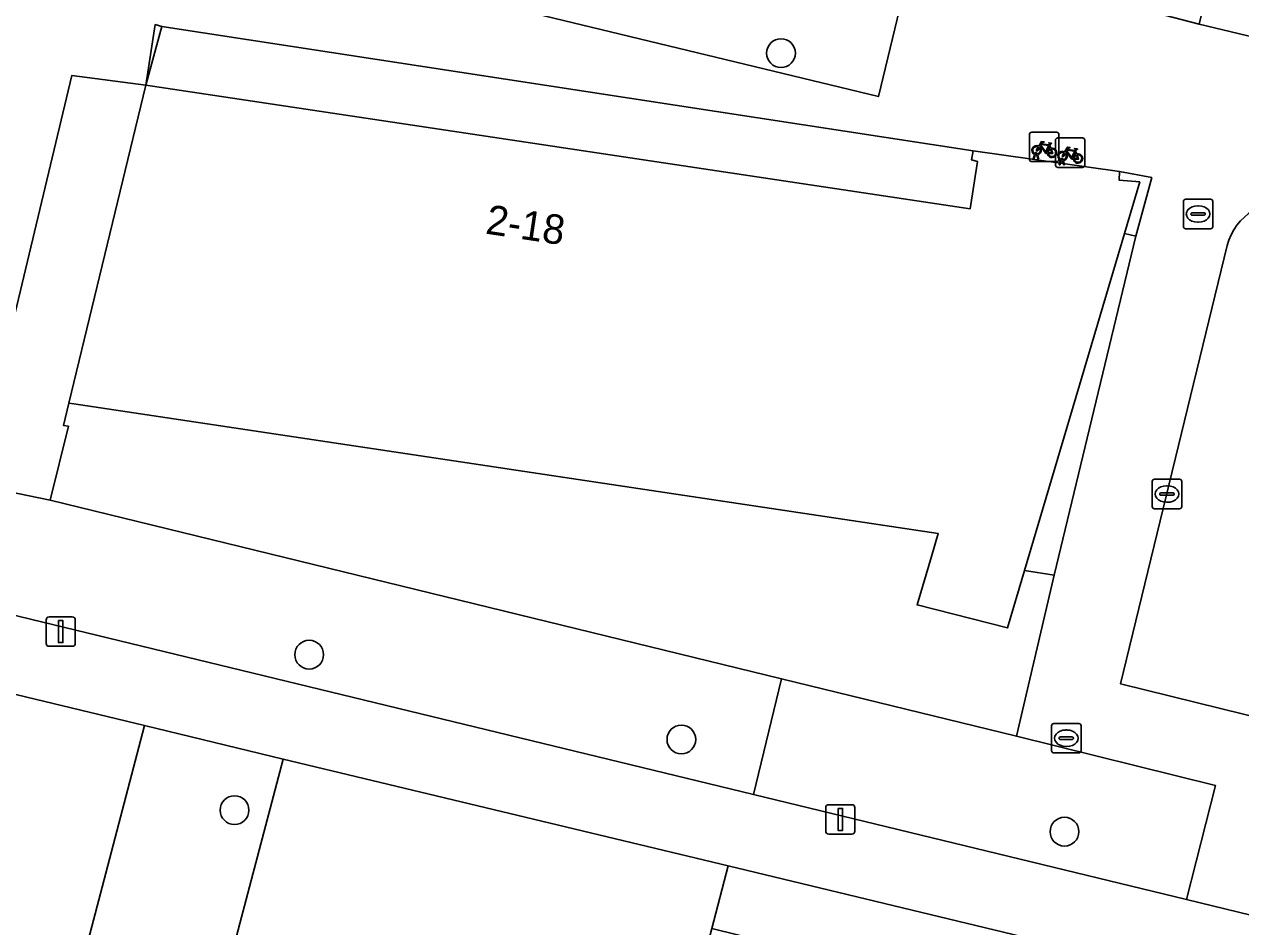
# Model space of a CAD drawing. Extents: x 162803 to 163818, y 381639 to 382475.
# Drawn here: x 163271.29 to 163312.66, y 382163.26 to 382193.93 of the extents above; entities that cross this region are included whole.
import ezdxf

# ---------------------------------------------------------------- set-up
doc = ezdxf.new("R2010")
doc.units = 0
for name, color, linetype in [('IMGEO_Boom', 7, 'Continuous'), ('IMGEO_Erf', 7, 'Continuous'), ('IMGEO_Fietsenrek', 7, 'Continuous'), ('IMGEO_Groenvoorziening', 7, 'Continuous'), ('IMGEO_Hek', 7, 'Continuous'), ('IMGEO_Kolk', 7, 'Continuous'), ('IMGEO_Lichtmast', 7, 'Continuous'), ('IMGEO_Pand', 7, 'Continuous'), ('IMGEO_Pand_nummerreeks', 7, 'Continuous'), ('IMGEO_Pand_overbouw', 7, 'Continuous'), ('IMGEO_Parkeervlak_open', 7, 'Continuous'), ('IMGEO_Rijbaan_lokaal_open', 7, 'Continuous'), ('IMGEO_Rioolput', 7, 'Continuous'), ('IMGEO_Voetpad_gesloten', 7, 'Continuous'), ('IMGEO_Voetpad_open', 7, 'Continuous')]:
    doc.layers.add(name, color=color, linetype=linetype)

msp = doc.modelspace()

# ---------------------------------------------------------------- linework, layer by layer
at = {"layer": 'IMGEO_Boom'}
for centre in [(163297.026, 382192.949), (163280.98, 382172.501), (163293.637, 382169.621), (163278.441, 382167.218), (163306.664, 382166.486)]:
    msp.add_circle(centre, 0.489, dxfattribs=at)
at = {"layer": 'IMGEO_Erf'}
msp.add_lwpolyline([(163272.981, 382181.029), (163272.811, 382181.055), (163272.627, 382180.291), (163272.792, 382180.266), (163272.171, 382177.751), (163297.042, 382171.68), (163305.036, 382169.729), (163306.317, 382175.199), (163305.301, 382175.36), (163304.723, 382173.413), (163301.65, 382174.195), (163302.138, 382175.838), (163302.37, 382176.619)], close=True, dxfattribs=at)
at = {"layer": 'IMGEO_Fietsenrek'}
for p, q in [((163305.476, 382189.335), (163305.476, 382190.176)), ((163305.476, 382190.176), (163305.476, 382189.335)), ((163305.551, 382190.26), (163306.392, 382190.26)), ((163306.392, 382190.26), (163305.551, 382190.26)), ((163306.476, 382190.185), (163306.476, 382189.344)), ((163306.476, 382189.344), (163306.476, 382190.185)), ((163306.163, 382189.809), (163306.199, 382189.714)), ((163306.358, 382189.141), (163306.358, 382189.982)), ((163306.358, 382189.982), (163306.358, 382189.141)), ((163306.433, 382190.066), (163307.274, 382190.066)), ((163307.274, 382190.066), (163306.433, 382190.066)), ((163307.358, 382189.991), (163307.358, 382189.15)), ((163307.358, 382189.15), (163307.358, 382189.991)), ((163305.603, 382189.344), (163305.642, 382189.504)), ((163305.672, 382189.492), (163305.637, 382189.344)), ((163305.714, 382189.516), (163305.713, 382189.52)), ((163305.755, 382189.344), (163305.721, 382189.486)), ((163305.745, 382189.527), (163305.746, 382189.52)), ((163305.753, 382189.49), (163305.788, 382189.344)), ((163307.045, 382189.615), (163307.081, 382189.52)), ((163306.401, 382189.26), (163305.56, 382189.26)), ((163305.56, 382189.26), (163306.401, 382189.26)), ((163305.637, 382189.344), (163305.603, 382189.344)), ((163305.788, 382189.344), (163305.755, 382189.344)), ((163307.283, 382189.066), (163306.442, 382189.066)), ((163306.442, 382189.066), (163307.283, 382189.066)), ((163306.485, 382189.15), (163306.524, 382189.31)), ((163306.519, 382189.15), (163306.485, 382189.15)), ((163306.554, 382189.298), (163306.519, 382189.15)), ((163306.596, 382189.322), (163306.595, 382189.326)), ((163306.637, 382189.15), (163306.603, 382189.292)), ((163306.627, 382189.333), (163306.628, 382189.326)), ((163306.635, 382189.296), (163306.67, 382189.15)), ((163306.67, 382189.15), (163306.637, 382189.15))]:
    msp.add_line(p, q, dxfattribs=at)
for points in [[(163305.81, 382189.734), (163305.758, 382189.644), (163305.718, 382189.619), (163305.719, 382189.666), (163305.774, 382189.76)], [(163305.789, 382189.786), (163305.884, 382189.95), (163305.97, 382189.936), (163305.972, 382189.927), (163305.916, 382189.916), (163305.889, 382189.871), (163306.145, 382189.83)], [(163306.085, 382189.542), (163306.035, 382189.542), (163305.844, 382189.793), (163305.825, 382189.761)], [(163306.132, 382189.805), (163305.875, 382189.846), (163305.858, 382189.817), (163306.025, 382189.597), (163306.132, 382189.805)], [(163306.18, 382189.707), (163306.15, 382189.784), (163306.041, 382189.566), (163306.084, 382189.566)], [(163306.145, 382189.83), (163306.17, 382189.879), (163306.164, 382189.883), (163306.141, 382189.887), (163306.129, 382189.894), (163306.128, 382189.897), (163306.13, 382189.902), (163306.225, 382189.887), (163306.227, 382189.877), (163306.217, 382189.864), (163306.205, 382189.858), (163306.191, 382189.864), (163306.163, 382189.809)], [(163306.114, 382189.566), (163306.234, 382189.565), (163306.19, 382189.679)], [(163306.21, 382189.686), (163306.265, 382189.541), (163306.115, 382189.541)], [(163306.692, 382189.54), (163306.64, 382189.45), (163306.6, 382189.425), (163306.601, 382189.472), (163306.656, 382189.566)], [(163306.671, 382189.592), (163306.766, 382189.756), (163306.852, 382189.742), (163306.854, 382189.733), (163306.798, 382189.722), (163306.771, 382189.677), (163307.027, 382189.636)], [(163306.967, 382189.348), (163306.917, 382189.348), (163306.726, 382189.599), (163306.707, 382189.567)], [(163307.014, 382189.611), (163306.757, 382189.652), (163306.74, 382189.623), (163306.907, 382189.403), (163307.014, 382189.611)], [(163307.062, 382189.513), (163307.032, 382189.59), (163306.923, 382189.372), (163306.966, 382189.372)], [(163306.996, 382189.372), (163307.116, 382189.371), (163307.072, 382189.485)], [(163307.092, 382189.492), (163307.147, 382189.347), (163306.997, 382189.347)], [(163307.027, 382189.636), (163307.052, 382189.685), (163307.046, 382189.689), (163307.023, 382189.693), (163307.011, 382189.7), (163307.01, 382189.703), (163307.012, 382189.708), (163307.107, 382189.693), (163307.109, 382189.683), (163307.099, 382189.67), (163307.087, 382189.664), (163307.073, 382189.67), (163307.045, 382189.615)]]:
    msp.add_lwpolyline(points, dxfattribs=at)
for centre, radius, start, end in [((163305.554, 382190.182), 0.0779, 92.4484, 184.2845), ((163305.554, 382190.182), 0.0779, 92.4484, 184.2845), ((163306.398, 382190.182), 0.0779, 2.4484, 94.2845), ((163306.398, 382190.182), 0.0779, 2.4484, 94.2845), ((163305.716, 382189.645), 0.159, 62.6766, 242.1369), ((163305.716, 382189.645), 0.129, 63.3192, 238.903), ((163305.716, 382189.645), 0.159, 283.5766, 46.6042), ((163306.436, 382189.988), 0.0779, 92.4484, 184.2845), ((163306.436, 382189.988), 0.0779, 92.4484, 184.2845), ((163307.28, 382189.988), 0.0779, 2.4484, 94.2845), ((163307.28, 382189.988), 0.0779, 2.4484, 94.2845), ((163305.696, 382189.516), 0.0499, 12.8025, 158.6934), ((163305.716, 382189.645), 0.159, 253.9967, 271.7867), ((163305.696, 382189.516), 0.0174, 12.8025, 163.4502), ((163305.716, 382189.645), 0.129, 253.415, 269.0204), ((163305.716, 382189.645), 0.129, 283.6043, 43.4302), ((163306.243, 382189.561), 0.159, 113.3408, 178.3217), ((163306.243, 382189.561), 0.159, 187.0065, 105.7708), ((163306.243, 382189.561), 0.129, 113.923, 177.9556), ((163306.243, 382189.561), 0.129, 188.6715, 104.5883), ((163306.598, 382189.451), 0.159, 62.6766, 242.1369), ((163306.598, 382189.451), 0.129, 63.3192, 238.903), ((163306.578, 382189.322), 0.0499, 12.8025, 158.6934), ((163306.598, 382189.451), 0.129, 283.6043, 43.4302), ((163306.598, 382189.451), 0.159, 283.5766, 46.6042), ((163307.125, 382189.367), 0.159, 113.3408, 178.3217), ((163307.125, 382189.367), 0.159, 187.0065, 105.7708), ((163307.125, 382189.367), 0.129, 113.923, 177.9556), ((163307.125, 382189.367), 0.129, 188.6715, 104.5883), ((163305.554, 382189.338), 0.0779, 182.4484, 274.2845), ((163305.554, 382189.338), 0.0779, 182.4484, 274.2845), ((163306.436, 382189.144), 0.0779, 182.4484, 274.2845), ((163306.436, 382189.144), 0.0779, 182.4484, 274.2845), ((163306.398, 382189.338), 0.0779, 272.4484, 4.2845), ((163306.398, 382189.338), 0.0779, 272.4484, 4.2845), ((163306.598, 382189.451), 0.159, 253.9967, 271.7867), ((163306.578, 382189.322), 0.0174, 12.8025, 163.4502), ((163306.598, 382189.451), 0.129, 253.415, 269.0204), ((163307.28, 382189.144), 0.0779, 272.4484, 4.2845), ((163307.28, 382189.144), 0.0779, 272.4484, 4.2845)]:
    msp.add_arc(centre, radius, start, end, dxfattribs=at)
at = {"layer": 'IMGEO_Groenvoorziening'}
for points in [[(163272.811, 382181.055), (163275.427, 382191.863), (163272.912, 382192.189), (163269.579, 382178.285), (163272.171, 382177.751), (163272.792, 382180.266), (163272.627, 382180.291)], [(163296.089, 382167.75), (163297.042, 382171.68), (163272.171, 382177.751), (163269.579, 382178.285), (163264.11, 382179.591), (163263.175, 382175.728)], [(163269.85, 382149.073), (163273.934, 382164.595), (163275.374, 382170.094), (163269.156, 382171.595), (163261.56, 382140.329), (163266.563, 382138.799), (163267.072, 382138.629)], [(163311.798, 382168.058), (163305.036, 382169.729), (163297.042, 382171.68), (163296.089, 382167.75), (163310.813, 382164.181)], [(163278.624, 382163.36), (163280.096, 382168.954), (163275.374, 382170.094), (163273.934, 382164.595), (163269.85, 382149.073), (163267.072, 382138.629), (163271.709, 382137.084), (163274.539, 382147.838)], [(163295.227, 382165.323), (163294.668, 382163.195), (163295.55, 382162.985), (163313.112, 382158.803), (163333.895, 382153.854), (163342.628, 382151.775), (163344.765, 382151.266), (163359.411, 382147.779), (163360.431, 382147.536), (163378.53, 382143.226), (163427.031, 382131.676), (163427.406, 382133.488), (163361, 382149.482), (163359.96, 382149.732), (163344.914, 382153.356), (163343.556, 382153.683), (163337.772, 382155.076), (163333.95, 382155.997)]]:
    msp.add_lwpolyline(points, close=True, dxfattribs=at)
msp.add_lwpolyline([(163312.197, 382186.407), (163308.573, 382171.509), (163318.73, 382169.011), (163322.331, 382183.982)], dxfattribs=at)
msp.add_arc((163314.184, 382185.87), 2.058, 80.2429, 164.8898, dxfattribs=at)
at = {"layer": 'IMGEO_Hek'}
msp.add_lwpolyline([(163297.042, 382171.68), (163296.089, 382167.75)], dxfattribs=at)
at = {"layer": 'IMGEO_Kolk'}
for p, q in [((163309.651, 382177.536), (163309.651, 382178.388)), ((163309.726, 382178.462), (163310.578, 382178.462)), ((163310.139, 382178.242), (163310.164, 382178.242)), ((163310.652, 382178.388), (163310.652, 382177.536)), ((163309.91, 382177.956), (163309.91, 382177.968)), ((163310.348, 382177.919), (163309.95, 382177.919)), ((163309.953, 382178.005), (163310.351, 382178.005)), ((163310.394, 382177.968), (163310.394, 382177.956)), ((163310.578, 382177.462), (163309.726, 382177.462)), ((163310.162, 382177.682), (163310.137, 382177.682))]:
    msp.add_line(p, q, dxfattribs=at)
for points in [[(163309.651, 382177.536), (163309.651, 382178.388)], [(163309.726, 382178.462), (163310.578, 382178.462)], [(163310.652, 382178.388), (163310.652, 382177.536)], [(163310.578, 382177.462), (163309.726, 382177.462)]]:
    msp.add_lwpolyline(points, dxfattribs=at)
for centre, radius, start, end in [((163309.728, 382178.386), 0.0765, 91.552, 178.448), ((163309.728, 382178.386), 0.0765, 91.552, 178.448), ((163310.576, 382178.386), 0.0765, 1.552, 88.448), ((163310.576, 382178.386), 0.0765, 1.552, 88.448), ((163309.95, 382177.965), 0.0403, 85.8775, 175.7526), ((163309.947, 382177.955), 0.0366, 178.938, 274.7102), ((163310.351, 382177.962), 0.043, 264.8664, 352.4533), ((163310.355, 382177.967), 0.0386, 1.7309, 96.639), ((163309.728, 382177.538), 0.0765, 181.552, 268.448), ((163309.728, 382177.538), 0.0765, 181.552, 268.448), ((163310.576, 382177.538), 0.0765, 271.552, 358.448), ((163310.576, 382177.538), 0.0765, 271.552, 358.448)]:
    msp.add_arc(centre, radius, start, end, dxfattribs=at)
for centre, major_axis, ratio, start_param, end_param in [((163310.138, 382177.962), (-0.387, 0.002), 0.722429, 4.712389, 7.853982), ((163310.163, 382177.962), (-0.39, 0.002), 0.717154, 1.570796, 4.712389)]:
    msp.add_ellipse(centre, major_axis=major_axis, ratio=ratio, start_param=start_param, end_param=end_param, dxfattribs=at)
at = {"layer": 'IMGEO_Lichtmast'}
for p, q in [((163272.034, 382172.887), (163272.034, 382173.687)), ((163272.034, 382173.687), (163272.034, 382172.887)), ((163272.134, 382173.787), (163272.924, 382173.787)), ((163272.924, 382173.787), (163272.134, 382173.787)), ((163273.024, 382173.687), (163273.024, 382172.887)), ((163273.024, 382172.887), (163273.024, 382173.687)), ((163272.924, 382172.787), (163272.134, 382172.787)), ((163272.134, 382172.787), (163272.924, 382172.787)), ((163298.547, 382166.504), (163298.547, 382167.304)), ((163298.547, 382167.304), (163298.547, 382166.504)), ((163298.647, 382167.404), (163299.437, 382167.404)), ((163299.437, 382167.404), (163298.647, 382167.404)), ((163299.537, 382167.304), (163299.537, 382166.504)), ((163299.537, 382166.504), (163299.537, 382167.304)), ((163299.437, 382166.404), (163298.647, 382166.404)), ((163298.647, 382166.404), (163299.437, 382166.404))]:
    msp.add_line(p, q, dxfattribs=at)
for points in [[(163272.454, 382173.662), (163272.604, 382173.662), (163272.604, 382172.912), (163272.454, 382172.912), (163272.454, 382173.662)], [(163298.967, 382167.279), (163299.117, 382167.279), (163299.117, 382166.529), (163298.967, 382166.529), (163298.967, 382167.279)]]:
    msp.add_lwpolyline(points, dxfattribs=at)
for centre, start, end in [((163272.134, 382173.687), 90, 180), ((163272.134, 382173.687), 90, 180), ((163272.924, 382173.687), 0, 90), ((163272.924, 382173.687), 360, 90), ((163272.134, 382172.887), 180, 270), ((163272.134, 382172.887), 180, 270), ((163272.924, 382172.887), 270, 0), ((163272.924, 382172.887), 270, 0), ((163298.647, 382167.304), 90, 180), ((163298.647, 382167.304), 90, 180), ((163299.437, 382167.304), 0, 90), ((163299.437, 382167.304), 360, 90), ((163298.647, 382166.504), 180, 270), ((163298.647, 382166.504), 180, 270), ((163299.437, 382166.504), 270, 0), ((163299.437, 382166.504), 270, 0)]:
    msp.add_arc(centre, 0.1, start, end, dxfattribs=at)
at = {"layer": 'IMGEO_Pand'}
msp.add_lwpolyline([(163305.301, 382175.36), (163308.701, 382186.815), (163309.223, 382188.572), (163308.524, 382188.631), (163308.534, 382188.925), (163303.556, 382189.624), (163303.504, 382189.319), (163303.712, 382189.26), (163303.455, 382187.657), (163275.427, 382191.863), (163272.811, 382181.055), (163272.981, 382181.029), (163302.37, 382176.619), (163302.138, 382175.838), (163301.65, 382174.195), (163304.723, 382173.413)], close=True, dxfattribs=at)
at = {"layer": 'IMGEO_Pand_overbouw'}
msp.add_lwpolyline([(163305.301, 382175.36), (163306.317, 382175.199), (163309.096, 382186.726), (163308.701, 382186.815)], close=True, dxfattribs=at)
at = {"layer": 'IMGEO_Parkeervlak_open'}
msp.add_lwpolyline([(163277.641, 382200.072), (163276.941, 382197.127), (163300.335, 382191.472), (163301.055, 382194.434)], dxfattribs=at)
at = {"layer": 'IMGEO_Rijbaan_lokaal_open'}
msp.add_lwpolyline([(163314.103, 382198.818), (163312.546, 382199.183), (163311.244, 382193.937), (163327.147, 382190.126), (163327.797, 382189.969), (163329, 382195.189), (163328.462, 382195.318)], dxfattribs=at)
at = {"layer": 'IMGEO_Rioolput'}
for p, q in [((163310.708, 382187.055), (163310.708, 382187.907)), ((163310.783, 382187.981), (163311.635, 382187.981)), ((163311.196, 382187.761), (163311.221, 382187.761)), ((163311.709, 382187.907), (163311.709, 382187.055)), ((163310.967, 382187.475), (163310.967, 382187.487)), ((163311.405, 382187.438), (163311.007, 382187.438)), ((163311.01, 382187.524), (163311.408, 382187.524)), ((163311.451, 382187.487), (163311.451, 382187.475)), ((163311.635, 382186.981), (163310.783, 382186.981)), ((163311.219, 382187.201), (163311.194, 382187.201)), ((163306.227, 382169.236), (163306.227, 382170.088)), ((163306.302, 382170.162), (163307.154, 382170.162)), ((163306.715, 382169.942), (163306.74, 382169.942)), ((163307.228, 382170.088), (163307.228, 382169.236)), ((163306.486, 382169.656), (163306.486, 382169.668)), ((163306.924, 382169.619), (163306.526, 382169.619)), ((163306.529, 382169.705), (163306.927, 382169.705)), ((163306.97, 382169.668), (163306.97, 382169.656)), ((163307.154, 382169.162), (163306.302, 382169.162)), ((163306.738, 382169.382), (163306.713, 382169.382))]:
    msp.add_line(p, q, dxfattribs=at)
for points in [[(163310.708, 382187.055), (163310.708, 382187.907)], [(163310.783, 382187.981), (163311.635, 382187.981)], [(163311.709, 382187.907), (163311.709, 382187.055)], [(163311.635, 382186.981), (163310.783, 382186.981)], [(163306.227, 382169.236), (163306.227, 382170.088)], [(163306.302, 382170.162), (163307.154, 382170.162)], [(163307.228, 382170.088), (163307.228, 382169.236)], [(163307.154, 382169.162), (163306.302, 382169.162)]]:
    msp.add_lwpolyline(points, dxfattribs=at)
for centre, radius, start, end in [((163310.785, 382187.905), 0.0765, 91.552, 178.448), ((163310.785, 382187.905), 0.0765, 91.552, 178.448), ((163311.633, 382187.905), 0.0765, 1.552, 88.448), ((163311.633, 382187.905), 0.0765, 1.552, 88.448), ((163311.007, 382187.484), 0.0403, 85.8775, 175.7526), ((163311.004, 382187.474), 0.0366, 178.938, 274.7102), ((163311.408, 382187.481), 0.043, 264.8664, 352.4533), ((163311.412, 382187.486), 0.0386, 1.7309, 96.639), ((163310.785, 382187.057), 0.0765, 181.552, 268.448), ((163310.785, 382187.057), 0.0765, 181.552, 268.448), ((163311.633, 382187.057), 0.0765, 271.552, 358.448), ((163311.633, 382187.057), 0.0765, 271.552, 358.448), ((163306.304, 382170.086), 0.0765, 91.552, 178.448), ((163306.304, 382170.086), 0.0765, 91.552, 178.448), ((163307.152, 382170.086), 0.0765, 1.552, 88.448), ((163307.152, 382170.086), 0.0765, 1.552, 88.448), ((163306.526, 382169.665), 0.0403, 85.8775, 175.7526), ((163306.523, 382169.655), 0.0366, 178.938, 274.7102), ((163306.927, 382169.662), 0.043, 264.8664, 352.4533), ((163306.931, 382169.667), 0.0386, 1.7309, 96.639), ((163306.304, 382169.238), 0.0765, 181.552, 268.448), ((163306.304, 382169.238), 0.0765, 181.552, 268.448), ((163307.152, 382169.238), 0.0765, 271.552, 358.448), ((163307.152, 382169.238), 0.0765, 271.552, 358.448)]:
    msp.add_arc(centre, radius, start, end, dxfattribs=at)
for centre, major_axis, ratio, start_param, end_param in [((163311.195, 382187.481), (-0.387, 0.002), 0.722429, 4.712389, 7.853982), ((163311.22, 382187.481), (-0.39, 0.002), 0.717154, 1.570796, 4.712389), ((163306.714, 382169.662), (-0.387, 0.002), 0.722429, 4.712389, 7.853982), ((163306.739, 382169.662), (-0.39, 0.002), 0.717154, 1.570796, 4.712389)]:
    msp.add_ellipse(centre, major_axis=major_axis, ratio=ratio, start_param=start_param, end_param=end_param, dxfattribs=at)
at = {"layer": 'IMGEO_Voetpad_gesloten'}
msp.add_lwpolyline([(163294.668, 382163.195), (163295.227, 382165.323), (163280.096, 382168.954), (163278.624, 382163.36), (163274.539, 382147.838), (163271.709, 382137.084), (163286.387, 382131.648)], close=True, dxfattribs=at)
at = {"layer": 'IMGEO_Voetpad_open'}
for points in [[(163301.055, 382194.434), (163300.335, 382191.472), (163276.941, 382197.127)], [(163327.147, 382190.126), (163311.244, 382193.937), (163308.883, 382194.55), (163303.237, 382195.89)], [(163269.579, 382178.285), (163272.912, 382192.189), (163275.427, 382191.863), (163275.745, 382193.917), (163275.974, 382193.848), (163303.556, 382189.624), (163308.534, 382188.925), (163309.631, 382188.717), (163309.096, 382186.726), (163308.701, 382186.815), (163305.301, 382175.36), (163306.317, 382175.199), (163305.036, 382169.729), (163311.798, 382168.058), (163310.813, 382164.181), (163314.355, 382163.32)], [(163322.331, 382183.982), (163318.73, 382169.011), (163308.573, 382171.509), (163312.197, 382186.407)], [(163296.089, 382167.75), (163263.175, 382175.728), (163259.647, 382176.573), (163257.82, 382177.025)], [(163251.556, 382175.845), (163256.094, 382174.749), (163266.24, 382172.299), (163269.156, 382171.595), (163275.374, 382170.094), (163280.096, 382168.954), (163295.227, 382165.323), (163333.95, 382155.997), (163337.772, 382155.076), (163338.36, 382157.513), (163314.355, 382163.32), (163310.813, 382164.181), (163296.089, 382167.75)]]:
    msp.add_lwpolyline(points, dxfattribs=at)
for points in [[(163275.427, 382191.863), (163275.974, 382193.848), (163275.745, 382193.917)], [(163275.974, 382193.848), (163275.427, 382191.863), (163303.455, 382187.657), (163303.712, 382189.26), (163303.504, 382189.319), (163303.556, 382189.624)], [(163308.534, 382188.925), (163308.524, 382188.631), (163309.223, 382188.572), (163308.701, 382186.815), (163309.096, 382186.726), (163309.631, 382188.717)]]:
    msp.add_lwpolyline(points, close=True, dxfattribs=at)
msp.add_arc((163314.184, 382185.87), 2.058, 80.2429, 164.8898, dxfattribs=at)

# ---------------------------------------------------------------- texts
at = {"layer": 'IMGEO_Pand_nummerreeks'}
msp.add_text('2-18', height=1, rotation=351.4656, dxfattribs=at).set_placement((163286.947, 382186.817))

doc.saveas('drawing.dxf')
